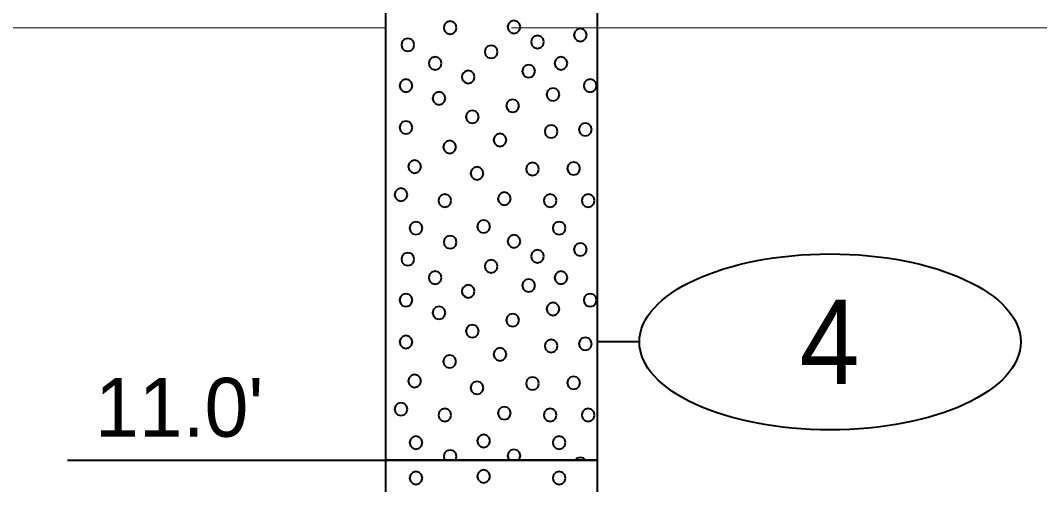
# Model space of a CAD drawing. Extents: x -582 to 653, y -817 to -3.
# Drawn here: x -29.8 to -17.73, y -499.54 to -494.04 of the extents above; entities that cross this region are included whole.
import ezdxf
from ezdxf.enums import TextEntityAlignment as Align

# ---------------------------------------------------------------- set-up
doc = ezdxf.new("R2010")
doc.units = 0
doc.header["$LTSCALE"] = 0.4
doc.layers.add('27', color=7, linetype='Continuous', lineweight=40)
doc.layers.add('7', color=7, linetype='Continuous', lineweight=13)

msp = doc.modelspace()

# ---------------------------------------------------------------- linework, layer by layer
at = {"layer": '27'}
for p, q in [((-22.4714, -497.8528), (-22.9714, -497.8528)), ((-29.2387, -499.2528), (-25.4713, -499.2528))]:
    msp.add_line(p, q, dxfattribs=at)
for points in [[(-25.4713, -493.7528), (-22.9713, -493.7528), (-22.9713, -499.2528), (-25.4713, -499.2528)], [(-24.6345, -494.1307), (-24.6447, -494.0926), (-24.6726, -494.0647), (-24.7107, -494.0545), (-24.7488, -494.0647), (-24.7767, -494.0926), (-24.7869, -494.1307), (-24.7767, -494.1688), (-24.7488, -494.1967), (-24.7107, -494.2069), (-24.6726, -494.1967), (-24.6447, -494.1688)], [(-23.8794, -494.1217), (-23.8896, -494.0836), (-23.9175, -494.0557), (-23.9556, -494.0455), (-23.9937, -494.0557), (-24.0216, -494.0836), (-24.0318, -494.1217), (-24.0216, -494.1598), (-23.9937, -494.1877), (-23.9556, -494.1979), (-23.9175, -494.1877), (-23.8896, -494.1598)], [(-23.6012, -494.299), (-23.6114, -494.2609), (-23.6393, -494.233), (-23.6774, -494.2228), (-23.7155, -494.233), (-23.7434, -494.2609), (-23.7536, -494.299), (-23.7434, -494.3371), (-23.7155, -494.365), (-23.6774, -494.3752), (-23.6393, -494.365), (-23.6114, -494.3371)], [(-23.0939, -494.2176), (-23.1041, -494.1795), (-23.132, -494.1516), (-23.1701, -494.1414), (-23.2082, -494.1516), (-23.2361, -494.1795), (-23.2463, -494.2176), (-23.2361, -494.2557), (-23.2082, -494.2836), (-23.1701, -494.2938), (-23.132, -494.2836), (-23.1041, -494.2557)], [(-25.1356, -494.3333), (-25.1458, -494.2952), (-25.1737, -494.2673), (-25.2118, -494.2571), (-25.2499, -494.2673), (-25.2778, -494.2952), (-25.288, -494.3333), (-25.2778, -494.3714), (-25.2499, -494.3993), (-25.2118, -494.4095), (-25.1737, -494.3993), (-25.1458, -494.3714)], [(-24.1495, -494.4165), (-24.1597, -494.3784), (-24.1876, -494.3505), (-24.2257, -494.3403), (-24.2638, -494.3505), (-24.2917, -494.3784), (-24.3019, -494.4165), (-24.2917, -494.4546), (-24.2638, -494.4825), (-24.2257, -494.4927), (-24.1876, -494.4825), (-24.1597, -494.4546)], [(-24.8127, -494.552), (-24.8229, -494.5139), (-24.8508, -494.486), (-24.8889, -494.4758), (-24.927, -494.486), (-24.9549, -494.5139), (-24.9651, -494.552), (-24.9549, -494.5901), (-24.927, -494.618), (-24.8889, -494.6282), (-24.8508, -494.618), (-24.8229, -494.5901)], [(-23.324, -494.552), (-23.3342, -494.5139), (-23.3621, -494.486), (-23.4002, -494.4758), (-23.4383, -494.486), (-23.4662, -494.5139), (-23.4764, -494.552), (-23.4662, -494.5901), (-23.4383, -494.618), (-23.4002, -494.6282), (-23.3621, -494.618), (-23.3342, -494.5901)], [(-23.7054, -494.6448), (-23.7156, -494.6067), (-23.7435, -494.5788), (-23.7816, -494.5686), (-23.8197, -494.5788), (-23.8476, -494.6067), (-23.8578, -494.6448), (-23.8476, -494.6829), (-23.8197, -494.7108), (-23.7816, -494.721), (-23.7435, -494.7108), (-23.7156, -494.6829)], [(-24.4211, -494.7134), (-24.4314, -494.6753), (-24.4592, -494.6474), (-24.4973, -494.6372), (-24.5354, -494.6474), (-24.5633, -494.6753), (-24.5735, -494.7134), (-24.5633, -494.7515), (-24.5354, -494.7794), (-24.4973, -494.7896), (-24.4592, -494.7794), (-24.4314, -494.7515)], [(-25.1585, -494.8177), (-25.1687, -494.7796), (-25.1966, -494.7517), (-25.2347, -494.7415), (-25.2728, -494.7517), (-25.3007, -494.7796), (-25.3109, -494.8177), (-25.3007, -494.8558), (-25.2728, -494.8837), (-25.2347, -494.8939), (-25.1966, -494.8837), (-25.1687, -494.8558)], [(-22.9783, -494.8177), (-22.9885, -494.7796), (-23.0164, -494.7517), (-23.0545, -494.7415), (-23.0926, -494.7517), (-23.1204, -494.7796), (-23.1307, -494.8177), (-23.1204, -494.8558), (-23.0926, -494.8837), (-23.0545, -494.8939), (-23.0164, -494.8837), (-22.9885, -494.8558)], [(-24.7669, -494.9677), (-24.7771, -494.9296), (-24.805, -494.9017), (-24.8431, -494.8915), (-24.8812, -494.9017), (-24.9091, -494.9296), (-24.9193, -494.9677), (-24.9091, -495.0058), (-24.8812, -495.0337), (-24.8431, -495.0439), (-24.805, -495.0337), (-24.7771, -495.0058)], [(-23.4168, -494.9219), (-23.4271, -494.8838), (-23.4549, -494.8559), (-23.493, -494.8457), (-23.5311, -494.8559), (-23.559, -494.8838), (-23.5692, -494.9219), (-23.559, -494.96), (-23.5311, -494.9879), (-23.493, -494.9981), (-23.4549, -494.9879), (-23.4271, -494.96)], [(-23.8948, -495.0554), (-23.905, -495.0173), (-23.9329, -494.9894), (-23.971, -494.9792), (-24.0091, -494.9894), (-24.037, -495.0173), (-24.0472, -495.0554), (-24.037, -495.0935), (-24.0091, -495.1214), (-23.971, -495.1316), (-23.9329, -495.1214), (-23.905, -495.0935)], [(-24.3728, -495.1863), (-24.383, -495.1482), (-24.4109, -495.1203), (-24.449, -495.1101), (-24.4871, -495.1203), (-24.515, -495.1482), (-24.5252, -495.1863), (-24.515, -495.2244), (-24.4871, -495.2523), (-24.449, -495.2625), (-24.4109, -495.2523), (-24.383, -495.2244)], [(-25.1585, -495.3135), (-25.1687, -495.2754), (-25.1966, -495.2475), (-25.2347, -495.2373), (-25.2728, -495.2475), (-25.3007, -495.2754), (-25.3109, -495.3135), (-25.3007, -495.3516), (-25.2728, -495.3794), (-25.2347, -495.3897), (-25.1966, -495.3794), (-25.1687, -495.3516)], [(-23.4397, -495.3605), (-23.4499, -495.3224), (-23.4778, -495.2945), (-23.5159, -495.2843), (-23.554, -495.2945), (-23.5819, -495.3224), (-23.5921, -495.3605), (-23.5819, -495.3986), (-23.554, -495.4265), (-23.5159, -495.4367), (-23.4778, -495.4265), (-23.4499, -495.3986)], [(-23.0355, -495.3363), (-23.0457, -495.2982), (-23.0736, -495.2704), (-23.1117, -495.2601), (-23.1498, -495.2704), (-23.1777, -495.2982), (-23.1879, -495.3363), (-23.1777, -495.3744), (-23.1498, -495.4023), (-23.1117, -495.4125), (-23.0736, -495.4023), (-23.0457, -495.3744)], [(-24.0449, -495.4609), (-24.0551, -495.4228), (-24.083, -495.3949), (-24.1211, -495.3847), (-24.1592, -495.3949), (-24.187, -495.4228), (-24.1973, -495.4609), (-24.187, -495.499), (-24.1592, -495.5269), (-24.1211, -495.5371), (-24.083, -495.5269), (-24.0551, -495.499)], [(-24.6398, -495.5448), (-24.65, -495.5067), (-24.6779, -495.4788), (-24.716, -495.4686), (-24.7541, -495.4788), (-24.782, -495.5067), (-24.7922, -495.5448), (-24.782, -495.5829), (-24.7541, -495.6108), (-24.716, -495.621), (-24.6779, -495.6108), (-24.65, -495.5829)], [(-25.0555, -495.7762), (-25.0657, -495.7381), (-25.0936, -495.7102), (-25.1317, -495.7), (-25.1698, -495.7102), (-25.1977, -495.7381), (-25.2079, -495.7762), (-25.1977, -495.8143), (-25.1698, -495.8422), (-25.1317, -495.8524), (-25.0936, -495.8422), (-25.0657, -495.8143)], [(-24.3169, -495.8563), (-24.3271, -495.8182), (-24.355, -495.7903), (-24.3931, -495.7801), (-24.4312, -495.7903), (-24.4591, -495.8182), (-24.4693, -495.8563), (-24.4591, -495.8944), (-24.4312, -495.9223), (-24.3931, -495.9325), (-24.355, -495.9223), (-24.3271, -495.8944)], [(-23.6597, -495.8054), (-23.6699, -495.7673), (-23.6978, -495.7394), (-23.7359, -495.7292), (-23.774, -495.7394), (-23.8018, -495.7673), (-23.8121, -495.8054), (-23.8018, -495.8435), (-23.774, -495.8714), (-23.7359, -495.8816), (-23.6978, -495.8714), (-23.6699, -495.8435)], [(-23.174, -495.7978), (-23.1842, -495.7597), (-23.2121, -495.7318), (-23.2502, -495.7216), (-23.2883, -495.7318), (-23.3162, -495.7597), (-23.3264, -495.7978), (-23.3162, -495.8359), (-23.2883, -495.8638), (-23.2502, -495.874), (-23.2121, -495.8638), (-23.1842, -495.8359)], [(-25.217, -496.1093), (-25.2272, -496.0712), (-25.2551, -496.0433), (-25.2932, -496.0331), (-25.3313, -496.0433), (-25.3592, -496.0712), (-25.3694, -496.1093), (-25.3592, -496.1474), (-25.3313, -496.1753), (-25.2932, -496.1855), (-25.2551, -496.1753), (-25.2272, -496.1474)], [(-24.6983, -496.1792), (-24.7085, -496.1411), (-24.7364, -496.1132), (-24.7745, -496.103), (-24.8126, -496.1132), (-24.8405, -496.1411), (-24.8507, -496.1792), (-24.8405, -496.2173), (-24.8126, -496.2452), (-24.7745, -496.2554), (-24.7364, -496.2452), (-24.7085, -496.2173)], [(-23.994, -496.1563), (-24.0042, -496.1182), (-24.0321, -496.0903), (-24.0702, -496.0801), (-24.1083, -496.0903), (-24.1362, -496.1182), (-24.1464, -496.1563), (-24.1362, -496.1944), (-24.1083, -496.2223), (-24.0702, -496.2325), (-24.0321, -496.2223), (-24.0042, -496.1944)], [(-23.4512, -496.1792), (-23.4614, -496.1411), (-23.4893, -496.1132), (-23.5274, -496.103), (-23.5655, -496.1132), (-23.5934, -496.1411), (-23.6036, -496.1792), (-23.5934, -496.2173), (-23.5655, -496.2452), (-23.5274, -496.2554), (-23.4893, -496.2452), (-23.4614, -496.2173)], [(-23.0011, -496.1792), (-23.0113, -496.1411), (-23.0392, -496.1132), (-23.0773, -496.103), (-23.1154, -496.1132), (-23.1433, -496.1411), (-23.1535, -496.1792), (-23.1433, -496.2173), (-23.1154, -496.2452), (-23.0773, -496.2554), (-23.0392, -496.2452), (-23.0113, -496.2173)], [(-25.0394, -496.5055), (-25.0496, -496.4674), (-25.0775, -496.4395), (-25.1156, -496.4293), (-25.1537, -496.4395), (-25.1816, -496.4674), (-25.1918, -496.5055), (-25.1816, -496.5436), (-25.1537, -496.5714), (-25.1156, -496.5817), (-25.0775, -496.5714), (-25.0496, -496.5436)], [(-24.2384, -496.4859), (-24.2487, -496.4478), (-24.2765, -496.4199), (-24.3146, -496.4097), (-24.3527, -496.4199), (-24.3806, -496.4478), (-24.3908, -496.4859), (-24.3806, -496.524), (-24.3527, -496.5519), (-24.3146, -496.5621), (-24.2765, -496.5519), (-24.2487, -496.524)], [(-23.3448, -496.5055), (-23.355, -496.4674), (-23.3829, -496.4395), (-23.421, -496.4293), (-23.4591, -496.4395), (-23.487, -496.4674), (-23.4972, -496.5055), (-23.487, -496.5436), (-23.4591, -496.5715), (-23.421, -496.5817), (-23.3829, -496.5715), (-23.355, -496.5436)], [(-24.6345, -496.6707), (-24.6447, -496.6326), (-24.6726, -496.6047), (-24.7107, -496.5945), (-24.7488, -496.6047), (-24.7767, -496.6326), (-24.7869, -496.6707), (-24.7767, -496.7088), (-24.7488, -496.7367), (-24.7107, -496.7469), (-24.6726, -496.7367), (-24.6447, -496.7088)], [(-23.8794, -496.6617), (-23.8896, -496.6236), (-23.9175, -496.5957), (-23.9556, -496.5855), (-23.9937, -496.5957), (-24.0216, -496.6236), (-24.0318, -496.6617), (-24.0216, -496.6998), (-23.9937, -496.7277), (-23.9556, -496.7379), (-23.9175, -496.7277), (-23.8896, -496.6998)], [(-23.6012, -496.839), (-23.6114, -496.8009), (-23.6393, -496.773), (-23.6774, -496.7628), (-23.7155, -496.773), (-23.7434, -496.8009), (-23.7536, -496.839), (-23.7434, -496.8771), (-23.7155, -496.905), (-23.6774, -496.9152), (-23.6393, -496.905), (-23.6114, -496.8771)], [(-23.0939, -496.7576), (-23.1041, -496.7195), (-23.132, -496.6916), (-23.1701, -496.6814), (-23.2082, -496.6916), (-23.2361, -496.7195), (-23.2463, -496.7576), (-23.2361, -496.7957), (-23.2082, -496.8236), (-23.1701, -496.8338), (-23.132, -496.8236), (-23.1041, -496.7957)], [(-25.1356, -496.8733), (-25.1458, -496.8352), (-25.1737, -496.8073), (-25.2118, -496.7971), (-25.2499, -496.8073), (-25.2778, -496.8352), (-25.288, -496.8733), (-25.2778, -496.9114), (-25.2499, -496.9393), (-25.2118, -496.9495), (-25.1737, -496.9393), (-25.1458, -496.9114)], [(-24.1495, -496.9565), (-24.1597, -496.9184), (-24.1876, -496.8905), (-24.2257, -496.8803), (-24.2638, -496.8905), (-24.2917, -496.9184), (-24.3019, -496.9565), (-24.2917, -496.9946), (-24.2638, -497.0225), (-24.2257, -497.0327), (-24.1876, -497.0225), (-24.1597, -496.9946)], [(-24.8127, -497.092), (-24.8229, -497.0539), (-24.8508, -497.026), (-24.8889, -497.0158), (-24.927, -497.026), (-24.9549, -497.0539), (-24.9651, -497.092), (-24.9549, -497.1301), (-24.927, -497.158), (-24.8889, -497.1682), (-24.8508, -497.158), (-24.8229, -497.1301)], [(-23.7054, -497.1848), (-23.7156, -497.1467), (-23.7435, -497.1188), (-23.7816, -497.1086), (-23.8197, -497.1188), (-23.8476, -497.1467), (-23.8578, -497.1848), (-23.8476, -497.2229), (-23.8197, -497.2508), (-23.7816, -497.261), (-23.7435, -497.2508), (-23.7156, -497.2229)], [(-23.324, -497.092), (-23.3342, -497.0539), (-23.3621, -497.026), (-23.4002, -497.0158), (-23.4383, -497.026), (-23.4662, -497.0539), (-23.4764, -497.092), (-23.4662, -497.1301), (-23.4383, -497.158), (-23.4002, -497.1682), (-23.3621, -497.158), (-23.3342, -497.1301)], [(-24.4211, -497.2534), (-24.4314, -497.2153), (-24.4592, -497.1874), (-24.4973, -497.1772), (-24.5354, -497.1874), (-24.5633, -497.2153), (-24.5735, -497.2534), (-24.5633, -497.2915), (-24.5354, -497.3194), (-24.4973, -497.3296), (-24.4592, -497.3194), (-24.4314, -497.2915)], [(-25.1585, -497.3577), (-25.1687, -497.3196), (-25.1966, -497.2917), (-25.2347, -497.2815), (-25.2728, -497.2917), (-25.3007, -497.3196), (-25.3109, -497.3577), (-25.3007, -497.3958), (-25.2728, -497.4237), (-25.2347, -497.4339), (-25.1966, -497.4237), (-25.1687, -497.3958)], [(-22.9783, -497.3577), (-22.9885, -497.3196), (-23.0164, -497.2917), (-23.0545, -497.2815), (-23.0926, -497.2917), (-23.1204, -497.3196), (-23.1307, -497.3577), (-23.1204, -497.3958), (-23.0926, -497.4237), (-23.0545, -497.4339), (-23.0164, -497.4237), (-22.9885, -497.3958)], [(-24.7669, -497.5077), (-24.7771, -497.4696), (-24.805, -497.4417), (-24.8431, -497.4315), (-24.8812, -497.4417), (-24.9091, -497.4696), (-24.9193, -497.5077), (-24.9091, -497.5458), (-24.8812, -497.5737), (-24.8431, -497.5839), (-24.805, -497.5737), (-24.7771, -497.5458)], [(-23.4168, -497.4619), (-23.4271, -497.4238), (-23.4549, -497.3959), (-23.493, -497.3857), (-23.5311, -497.3959), (-23.559, -497.4238), (-23.5692, -497.4619), (-23.559, -497.5), (-23.5311, -497.5279), (-23.493, -497.5381), (-23.4549, -497.5279), (-23.4271, -497.5)], [(-23.8948, -497.5954), (-23.905, -497.5573), (-23.9329, -497.5294), (-23.971, -497.5192), (-24.0091, -497.5294), (-24.037, -497.5573), (-24.0472, -497.5954), (-24.037, -497.6335), (-24.0091, -497.6614), (-23.971, -497.6716), (-23.9329, -497.6614), (-23.905, -497.6335)], [(-24.3728, -497.7263), (-24.383, -497.6882), (-24.4109, -497.6603), (-24.449, -497.6501), (-24.4871, -497.6603), (-24.515, -497.6882), (-24.5252, -497.7263), (-24.515, -497.7644), (-24.4871, -497.7923), (-24.449, -497.8025), (-24.4109, -497.7923), (-24.383, -497.7644)], [(-25.1585, -497.8535), (-25.1687, -497.8154), (-25.1966, -497.7875), (-25.2347, -497.7773), (-25.2728, -497.7875), (-25.3007, -497.8154), (-25.3109, -497.8535), (-25.3007, -497.8916), (-25.2728, -497.9194), (-25.2347, -497.9297), (-25.1966, -497.9194), (-25.1687, -497.8916)], [(-23.4397, -497.9005), (-23.4499, -497.8624), (-23.4778, -497.8345), (-23.5159, -497.8243), (-23.554, -497.8345), (-23.5819, -497.8624), (-23.5921, -497.9005), (-23.5819, -497.9386), (-23.554, -497.9665), (-23.5159, -497.9767), (-23.4778, -497.9665), (-23.4499, -497.9386)], [(-23.0355, -497.8763), (-23.0457, -497.8382), (-23.0736, -497.8104), (-23.1117, -497.8001), (-23.1498, -497.8104), (-23.1777, -497.8382), (-23.1879, -497.8763), (-23.1777, -497.9144), (-23.1498, -497.9423), (-23.1117, -497.9525), (-23.0736, -497.9423), (-23.0457, -497.9144)], [(-24.0449, -498.0009), (-24.0551, -497.9628), (-24.083, -497.9349), (-24.1211, -497.9247), (-24.1592, -497.9349), (-24.187, -497.9628), (-24.1973, -498.0009), (-24.187, -498.039), (-24.1592, -498.0669), (-24.1211, -498.0771), (-24.083, -498.0669), (-24.0551, -498.039)], [(-24.6398, -498.0848), (-24.65, -498.0467), (-24.6779, -498.0188), (-24.716, -498.0086), (-24.7541, -498.0188), (-24.782, -498.0467), (-24.7922, -498.0848), (-24.782, -498.1229), (-24.7541, -498.1508), (-24.716, -498.161), (-24.6779, -498.1508), (-24.65, -498.1229)], [(-25.0555, -498.3162), (-25.0657, -498.2781), (-25.0936, -498.2502), (-25.1317, -498.24), (-25.1698, -498.2502), (-25.1977, -498.2781), (-25.2079, -498.3162), (-25.1977, -498.3543), (-25.1698, -498.3822), (-25.1317, -498.3924), (-25.0936, -498.3822), (-25.0657, -498.3543)], [(-24.3169, -498.3963), (-24.3271, -498.3582), (-24.355, -498.3303), (-24.3931, -498.3201), (-24.4312, -498.3303), (-24.4591, -498.3582), (-24.4693, -498.3963), (-24.4591, -498.4344), (-24.4312, -498.4623), (-24.3931, -498.4725), (-24.355, -498.4623), (-24.3271, -498.4344)], [(-23.6597, -498.3454), (-23.6699, -498.3073), (-23.6978, -498.2794), (-23.7359, -498.2692), (-23.774, -498.2794), (-23.8018, -498.3073), (-23.8121, -498.3454), (-23.8018, -498.3835), (-23.774, -498.4114), (-23.7359, -498.4216), (-23.6978, -498.4114), (-23.6699, -498.3835)], [(-23.174, -498.3378), (-23.1842, -498.2997), (-23.2121, -498.2718), (-23.2502, -498.2616), (-23.2883, -498.2718), (-23.3162, -498.2997), (-23.3264, -498.3378), (-23.3162, -498.3759), (-23.2883, -498.4038), (-23.2502, -498.414), (-23.2121, -498.4038), (-23.1842, -498.3759)], [(-25.217, -498.6493), (-25.2272, -498.6112), (-25.2551, -498.5833), (-25.2932, -498.5731), (-25.3313, -498.5833), (-25.3592, -498.6112), (-25.3694, -498.6493), (-25.3592, -498.6874), (-25.3313, -498.7153), (-25.2932, -498.7255), (-25.2551, -498.7153), (-25.2272, -498.6874)], [(-24.6983, -498.7192), (-24.7085, -498.6811), (-24.7364, -498.6532), (-24.7745, -498.643), (-24.8126, -498.6532), (-24.8405, -498.6811), (-24.8507, -498.7192), (-24.8405, -498.7573), (-24.8126, -498.7852), (-24.7745, -498.7954), (-24.7364, -498.7852), (-24.7085, -498.7573)], [(-23.994, -498.6963), (-24.0042, -498.6582), (-24.0321, -498.6303), (-24.0702, -498.6201), (-24.1083, -498.6303), (-24.1362, -498.6582), (-24.1464, -498.6963), (-24.1362, -498.7344), (-24.1083, -498.7623), (-24.0702, -498.7725), (-24.0321, -498.7623), (-24.0042, -498.7344)], [(-23.4512, -498.7192), (-23.4614, -498.6811), (-23.4893, -498.6532), (-23.5274, -498.643), (-23.5655, -498.6532), (-23.5934, -498.6811), (-23.6036, -498.7192), (-23.5934, -498.7573), (-23.5655, -498.7852), (-23.5274, -498.7954), (-23.4893, -498.7852), (-23.4614, -498.7573)], [(-23.0011, -498.7192), (-23.0113, -498.6811), (-23.0392, -498.6532), (-23.0773, -498.643), (-23.1154, -498.6532), (-23.1433, -498.6811), (-23.1535, -498.7192), (-23.1433, -498.7573), (-23.1154, -498.7852), (-23.0773, -498.7954), (-23.0392, -498.7852), (-23.0113, -498.7573)], [(-25.0394, -499.0455), (-25.0496, -499.0074), (-25.0775, -498.9795), (-25.1156, -498.9693), (-25.1537, -498.9795), (-25.1816, -499.0074), (-25.1918, -499.0455), (-25.1816, -499.0836), (-25.1537, -499.1114), (-25.1156, -499.1217), (-25.0775, -499.1114), (-25.0496, -499.0836)], [(-24.2384, -499.0259), (-24.2487, -498.9878), (-24.2765, -498.9599), (-24.3146, -498.9497), (-24.3527, -498.9599), (-24.3806, -498.9878), (-24.3908, -499.0259), (-24.3806, -499.064), (-24.3527, -499.0919), (-24.3146, -499.1021), (-24.2765, -499.0919), (-24.2487, -499.064)], [(-23.3448, -499.0455), (-23.355, -499.0074), (-23.3829, -498.9795), (-23.421, -498.9693), (-23.4591, -498.9795), (-23.487, -499.0074), (-23.4972, -499.0455), (-23.487, -499.0836), (-23.4591, -499.1115), (-23.421, -499.1217), (-23.3829, -499.1115), (-23.355, -499.0836)], [(-24.6447, -499.2488), (-24.6345, -499.2107), (-24.6447, -499.1726), (-24.6726, -499.1447), (-24.7107, -499.1345), (-24.7488, -499.1447), (-24.7767, -499.1726), (-24.7869, -499.2107), (-24.7767, -499.2488), (-24.7727, -499.2528), (-24.6487, -499.2528)], [(-23.8896, -499.2398), (-23.8794, -499.2017), (-23.8896, -499.1636), (-23.9175, -499.1357), (-23.9556, -499.1255), (-23.9937, -499.1357), (-24.0216, -499.1636), (-24.0318, -499.2017), (-24.0216, -499.2398), (-24.0086, -499.2528), (-23.9026, -499.2528)], [(-25.4713, -499.2528), (-22.9713, -499.2528), (-22.9713, -514.2528), (-25.4713, -514.2528)], [(-23.132, -499.2316), (-23.1701, -499.2214), (-23.2082, -499.2316), (-23.2294, -499.2528), (-23.1108, -499.2528)], [(-25.0394, -499.4655), (-25.0496, -499.4274), (-25.0775, -499.3995), (-25.1156, -499.3893), (-25.1537, -499.3995), (-25.1816, -499.4274), (-25.1918, -499.4655), (-25.1816, -499.5036), (-25.1537, -499.5314), (-25.1156, -499.5417), (-25.0775, -499.5314), (-25.0496, -499.5036)], [(-24.2384, -499.4459), (-24.2487, -499.4078), (-24.2765, -499.3799), (-24.3146, -499.3697), (-24.3527, -499.3799), (-24.3806, -499.4078), (-24.3908, -499.4459), (-24.3806, -499.484), (-24.3527, -499.5119), (-24.3146, -499.5221), (-24.2765, -499.5119), (-24.2487, -499.484)], [(-23.3448, -499.4655), (-23.355, -499.4274), (-23.3829, -499.3995), (-23.421, -499.3893), (-23.4591, -499.3995), (-23.487, -499.4274), (-23.4972, -499.4655), (-23.487, -499.5036), (-23.4591, -499.5315), (-23.421, -499.5417), (-23.3829, -499.5315), (-23.355, -499.5036)]]:
    msp.add_lwpolyline(points, close=True, dxfattribs=at)
msp.add_ellipse((-20.214, -497.8528), major_axis=(2.2574, 0), ratio=0.461538, dxfattribs=at)
at = {"layer": '7'}
for p, q in [((-62.9147, -494.1328), (-25.4713, -494.1328)), ((-23.9857, -494.1328), (27.5287, -494.1328)), ((-22.9713, -494.1328), (28.379, -494.1328))]:
    msp.add_line(p, q, dxfattribs=at)

# ---------------------------------------------------------------- texts
at = {"layer": '27', "width": 0.95}
msp.add_text('4', height=1, dxfattribs=at).set_placement((-20.2213, -498.3528), align=Align.CENTER)
at = {"layer": '27'}
msp.add_text("11.0'", height=0.6976, dxfattribs=at).set_placement((-28.9146, -498.9764))

doc.saveas('drawing.dxf')
